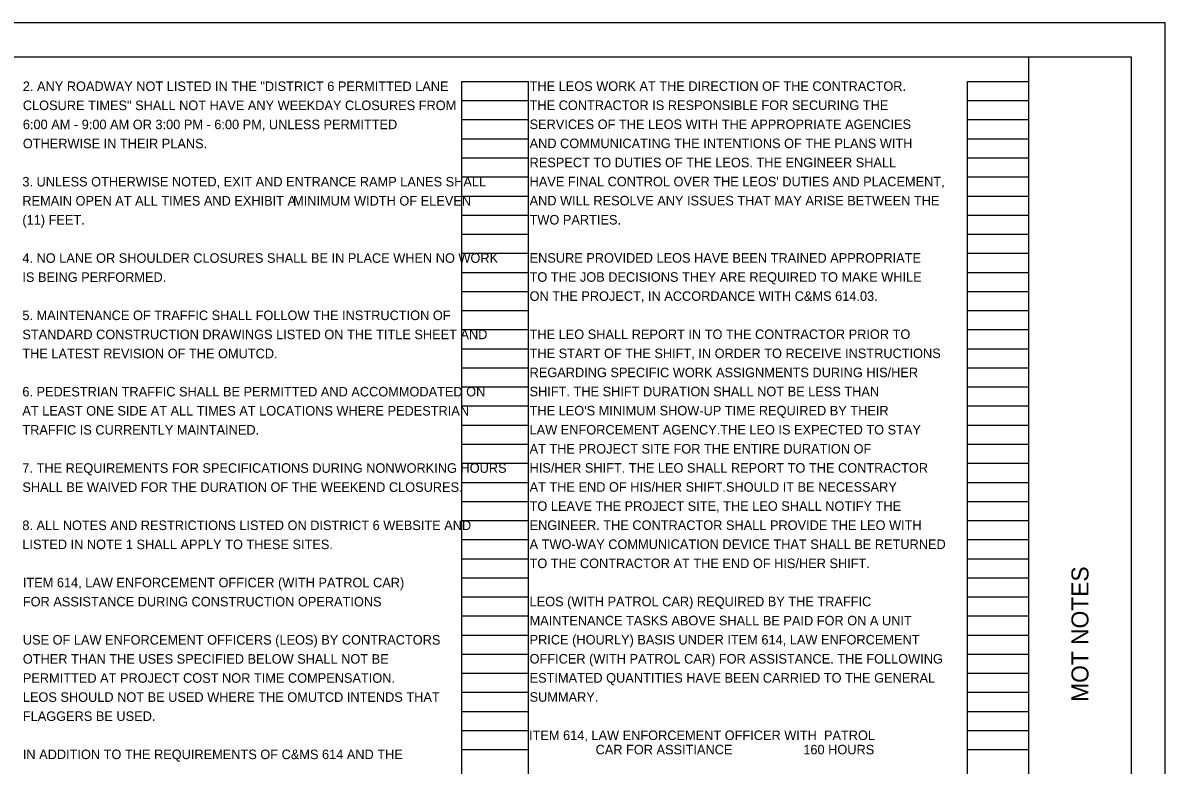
# Model space of a CAD drawing. Extents: x 0 to 34, y 0 to 22.
# Drawn here: x 17.24 to 34, y 11.11 to 22 of the extents above; entities that cross this region are included whole.
import ezdxf

# ---------------------------------------------------------------- set-up
doc = ezdxf.new("R2010")
doc.units = 0
for name, color, linetype in [('SH_Border', 7, 'Continuous'), ('SH_Cut_Line', 7, 'Continuous'), ('SH_Data', 7, 'Continuous'), ('SH_Text', 7, 'Continuous')]:
    doc.layers.add(name, color=color, linetype=linetype)

msp = doc.modelspace()

# ---------------------------------------------------------------- linework, layer by layer
at = {"layer": 'SH_Border'}
msp.add_line((32, 0.5), (32, 21.5), dxfattribs=at)
msp.add_lwpolyline([(1.5, 21.5), (33.5, 21.5), (33.5, 0.5), (1.5, 0.5)], close=True, dxfattribs=at)
at = {"layer": 'SH_Cut_Line'}
msp.add_lwpolyline([(0, 0), (34, 0), (34, 22), (0, 22)], close=True, dxfattribs=at)
at = {"layer": 'SH_Data'}
for p, q in [((23.68, 0.98), (23.68, 21.14)), ((23.68, 21.14), (24.66, 21.14)), ((24.66, 0.98), (24.66, 21.14)), ((31.1, 0.98), (31.1, 21.14)), ((31.1, 21.14), (32, 21.14)), ((32, 0.98), (32, 21.14)), ((23.68, 20.86), (24.66, 20.86)), ((31.1, 20.86), (32, 20.86)), ((23.68, 20.58), (24.66, 20.58)), ((31.1, 20.58), (32, 20.58)), ((23.68, 20.3), (24.66, 20.3)), ((31.1, 20.3), (32, 20.3)), ((23.68, 20.02), (24.66, 20.02)), ((31.1, 20.02), (32, 20.02)), ((23.68, 19.74), (24.66, 19.74)), ((31.1, 19.74), (32, 19.74)), ((23.68, 19.46), (24.66, 19.46)), ((31.1, 19.46), (32, 19.46)), ((23.68, 19.18), (24.66, 19.18)), ((31.1, 19.18), (32, 19.18)), ((23.68, 18.9), (24.66, 18.9)), ((31.1, 18.9), (32, 18.9)), ((23.68, 18.62), (24.66, 18.62)), ((31.1, 18.62), (32, 18.62)), ((23.68, 18.34), (24.66, 18.34)), ((31.1, 18.34), (32, 18.34)), ((23.68, 18.06), (24.66, 18.06)), ((31.1, 18.06), (32, 18.06)), ((23.68, 17.78), (24.66, 17.78)), ((31.1, 17.78), (32, 17.78)), ((23.68, 17.5), (24.66, 17.5)), ((31.1, 17.5), (32, 17.5)), ((23.68, 17.22), (24.66, 17.22)), ((31.1, 17.22), (32, 17.22)), ((23.68, 16.94), (24.66, 16.94)), ((31.1, 16.94), (32, 16.94)), ((23.68, 16.66), (24.66, 16.66)), ((31.1, 16.66), (32, 16.66)), ((23.68, 16.38), (24.66, 16.38)), ((31.1, 16.38), (32, 16.38)), ((23.68, 16.1), (24.66, 16.1)), ((31.1, 16.1), (32, 16.1)), ((23.68, 15.82), (24.66, 15.82)), ((31.1, 15.82), (32, 15.82)), ((23.68, 15.54), (24.66, 15.54)), ((31.1, 15.54), (32, 15.54)), ((23.68, 15.26), (24.66, 15.26)), ((31.1, 15.26), (32, 15.26)), ((23.68, 14.98), (24.66, 14.98)), ((31.1, 14.98), (32, 14.98)), ((23.68, 14.7), (24.66, 14.7)), ((31.1, 14.7), (32, 14.7)), ((23.68, 14.42), (24.66, 14.42)), ((31.1, 14.42), (32, 14.42)), ((23.68, 14.14), (24.66, 14.14)), ((31.1, 14.14), (32, 14.14)), ((23.68, 13.86), (24.66, 13.86)), ((31.1, 13.86), (32, 13.86)), ((23.68, 13.58), (24.66, 13.58)), ((31.1, 13.58), (32, 13.58)), ((23.68, 13.3), (24.66, 13.3)), ((31.1, 13.3), (32, 13.3)), ((23.68, 13.02), (24.66, 13.02)), ((31.1, 13.02), (32, 13.02)), ((23.68, 12.74), (24.66, 12.74)), ((31.1, 12.74), (32, 12.74)), ((23.68, 12.46), (24.66, 12.46)), ((31.1, 12.46), (32, 12.46)), ((23.68, 12.18), (24.66, 12.18)), ((31.1, 12.18), (32, 12.18)), ((23.68, 11.9), (24.66, 11.9)), ((31.1, 11.9), (32, 11.9)), ((23.68, 11.62), (24.66, 11.62)), ((31.1, 11.62), (32, 11.62)), ((23.68, 11.34), (24.66, 11.34)), ((31.1, 11.34), (32, 11.34))]:
    msp.add_line(p, q, dxfattribs=at)

# ---------------------------------------------------------------- texts
msp.add_text('MOT NOTES', height=0.25, rotation=90, dxfattribs=at).set_placement((32.875, 12.04))
at = {"layer": 'SH_Text'}
for s, p in [('2. ANY ROADWAY NOT LISTED IN THE "DISTRICT 6 PERMITTED LANE ', (17.24, 21)), ('THE LEOS WORK AT THE DIRECTION OF THE CONTRACTOR.', (24.675, 21.002)), ('CLOSURE TIMES" SHALL NOT HAVE ANY WEEKDAY CLOSURES FROM ', (17.24, 20.72)), ('THE CONTRACTOR IS RESPONSIBLE FOR SECURING THE', (24.675, 20.722)), ('6:00 AM - 9:00 AM OR 3:00 PM - 6:00 PM, UNLESS PERMITTED ', (17.24, 20.44)), ('SERVICES OF THE LEOS WITH THE APPROPRIATE AGENCIES', (24.675, 20.442)), ('OTHERWISE IN THEIR PLANS.', (17.24, 20.16)), ('AND COMMUNICATING THE INTENTIONS OF THE PLANS WITH', (24.675, 20.162)), ('RESPECT TO DUTIES OF THE LEOS. THE ENGINEER SHALL', (24.675, 19.882)), ('3. UNLESS OTHERWISE NOTED, EXIT AND ENTRANCE RAMP LANES SHALL ', (17.233, 19.6)), ("HAVE FINAL CONTROL OVER THE LEOS' DUTIES AND PLACEMENT,", (24.675, 19.602)), ('REMAIN OPEN AT ALL TIMES AND EXHIBIT A', (17.233, 19.32)), (' MINIMUM WIDTH OF ELEVEN ', (21.153, 19.32)), ('AND WILL RESOLVE ANY ISSUES THAT MAY ARISE BETWEEN THE', (24.675, 19.322)), ('(11) FEET. ', (17.233, 19.04)), ('TWO PARTIES.', (24.675, 19.042)), ('4. NO LANE OR SHOULDER CLOSURES SHALL BE IN PLACE WHEN NO WORK', (17.233, 18.48)), ('ENSURE PROVIDED LEOS HAVE BEEN TRAINED APPROPRIATE', (24.675, 18.482)), ('IS BEING PERFORMED.', (17.233, 18.2)), ('TO THE JOB DECISIONS THEY ARE REQUIRED TO MAKE WHILE', (24.675, 18.202)), ('ON THE PROJECT, IN ACCORDANCE WITH C&MS 614.03.', (24.675, 17.922)), ('5. MAINTENANCE OF TRAFFIC SHALL FOLLOW THE INSTRUCTION OF ', (17.233, 17.64)), ('STANDARD CONSTRUCTION DRAWINGS LISTED ON THE TITLE SHEET AND ', (17.233, 17.36)), ('THE LEO SHALL REPORT IN TO THE CONTRACTOR PRIOR TO', (24.675, 17.362)), ('THE LATEST REVISION OF THE OMUTCD.', (17.233, 17.08)), ('THE START OF THE SHIFT, IN ORDER TO RECEIVE INSTRUCTIONS', (24.675, 17.082)), ('REGARDING SPECIFIC WORK ASSIGNMENTS DURING HIS/HER', (24.675, 16.802)), ('6. PEDESTRIAN TRAFFIC SHALL BE PERMITTED AND ACCOMMODATED ON ', (17.233, 16.52)), ('SHIFT. THE SHIFT DURATION SHALL NOT BE LESS THAN', (24.675, 16.522)), ('AT LEAST ONE SIDE AT ALL TIMES AT LOCATIONS WHERE PEDESTRIAN ', (17.233, 16.24)), ("THE LEO'S MINIMUM SHOW-UP TIME REQUIRED BY THEIR", (24.675, 16.242)), ('TRAFFIC IS CURRENTLY MAINTAINED.', (17.233, 15.96)), ('LAW ENFORCEMENT AGENCY.THE LEO IS EXPECTED TO STAY', (24.675, 15.962)), ('AT THE PROJECT SITE FOR THE ENTIRE DURATION OF', (24.675, 15.682)), ('7. THE REQUIREMENTS FOR SPECIFICATIONS DURING NONWORKING HOURS ', (17.233, 15.4)), ('HIS/HER SHIFT. THE LEO SHALL REPORT TO THE CONTRACTOR', (24.675, 15.402)), ('SHALL BE WAIVED FOR THE DURATION OF THE WEEKEND CLOSURES.', (17.233, 15.12)), ('AT THE END OF HIS/HER SHIFT.SHOULD IT BE NECESSARY', (24.675, 15.122)), ('TO LEAVE THE PROJECT SITE, THE LEO SHALL NOTIFY THE', (24.675, 14.842)), ('8. ALL NOTES AND RESTRICTIONS LISTED ON DISTRICT 6 WEBSITE AND ', (17.233, 14.56)), ('ENGINEER. THE CONTRACTOR SHALL PROVIDE THE LEO WITH', (24.675, 14.562)), ('LISTED IN NOTE 1 SHALL APPLY TO THESE SITES.', (17.233, 14.28)), ('A TWO-WAY COMMUNICATION DEVICE THAT SHALL BE RETURNED', (24.675, 14.282)), ('TO THE CONTRACTOR AT THE END OF HIS/HER SHIFT.', (24.675, 14.002)), ('ITEM 614, LAW ENFORCEMENT OFFICER (WITH PATROL CAR)', (17.24, 13.72)), ('FOR ASSISTANCE DURING CONSTRUCTION OPERATIONS', (17.24, 13.44)), ('LEOS (WITH PATROL CAR) REQUIRED BY THE TRAFFIC', (24.675, 13.442)), ('MAINTENANCE TASKS ABOVE SHALL BE PAID FOR ON A UNIT', (24.675, 13.162)), ('USE OF LAW ENFORCEMENT OFFICERS (LEOS) BY CONTRACTORS', (17.24, 12.88)), ('PRICE (HOURLY) BASIS UNDER ITEM 614, LAW ENFORCEMENT', (24.675, 12.882)), ('OTHER THAN THE USES SPECIFIED BELOW SHALL NOT BE', (17.24, 12.6)), ('OFFICER (WITH PATROL CAR) FOR ASSISTANCE. THE FOLLOWING', (24.675, 12.602)), ('PERMITTED AT PROJECT COST NOR TIME COMPENSATION.', (17.24, 12.32)), ('ESTIMATED QUANTITIES HAVE BEEN CARRIED TO THE GENERAL', (24.675, 12.322)), ('LEOS SHOULD NOT BE USED WHERE THE OMUTCD INTENDS THAT', (17.24, 12.04)), ('SUMMARY.', (24.675, 12.042)), ('FLAGGERS BE USED.', (17.24, 11.76)), ('ITEM 614, LAW ENFORCEMENT OFFICER WITH  PATROL', (24.667, 11.48)), ('        CAR FOR ASSITIANCE                    160 HOURS', (25.227, 11.27)), ('IN ADDITION TO THE REQUIREMENTS OF C&MS 614 AND THE', (17.24, 11.2))]:
    msp.add_text(s, height=0.14, dxfattribs=at).set_placement(p)

doc.saveas('drawing.dxf')
